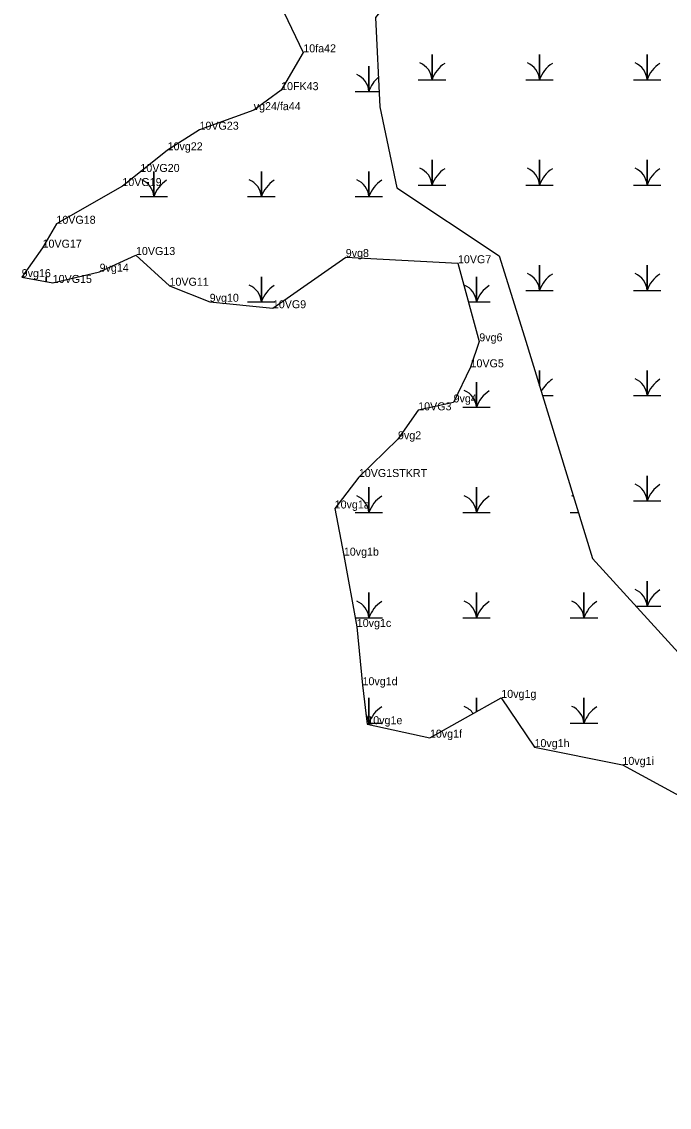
# Model space of a CAD drawing. Extents: x 2072529 to 2268796, y 436423 to 470397.
# Drawn here: x 2218413 to 2218818, y 449255 to 449933 of the extents above; entities that cross this region are included whole.
import ezdxf

# ---------------------------------------------------------------- set-up
doc = ezdxf.new("R2010")
doc.units = 0
for name, color, linetype in [('Exist Environmental Wetland Boundary', 7, 'Continuous'), ('Exist Environmental Wetland Boundary Cogo Comment', 7, 'Continuous'), ('Exist Environmental Wetland Boundary Cogo Point CELL', 7, 'Continuous'), ('Exist Hydro Jurisdictional Stream or Body of Water NEU Mitigable', 7, 'Continuous'), ('Exist Hydro Swamp or Marsh', 7, 'Continuous')]:
    doc.layers.add(name, color=color, linetype=linetype)

msp = doc.modelspace()

# ---------------------------------------------------------------- linework, layer by layer
at = {"layer": 'Exist Environmental Wetland Boundary'}
for points in [[(2218576.58, 449938.89), (2218588.8, 449913.82), (2218574.92, 449890.19), (2218557.81, 449877.7), (2218523.88, 449865.47), (2218503.95, 449852.61), (2218486.91, 449839.08), (2218475.66, 449830.27), (2218434.4, 449806.7), (2218425.75, 449791.75), (2218412.7, 449773.34), (2218432.08, 449769.73), (2218461.44, 449776.76), (2218484.17, 449787.18), (2218505.14, 449767.97), (2218530.27, 449757.96), (2218569.77, 449753.92), (2218615.36, 449785.92), (2218685.51, 449782.04), (2218698.88, 449733.24), (2218693.38, 449717.01), (2218682.81, 449695.07), (2218660.66, 449690.13), (2218648.02, 449672.03), (2218623.54, 449648.45)], [(2218623.54, 449648.45), (2218608.43, 449628.79), (2218614.15, 449599.32), (2218622.25, 449554.75), (2218625.83, 449518.36), (2218628.83, 449494), (2218667.98, 449485.58), (2218712.63, 449510.45), (2218733.38, 449479.68), (2218788.37, 449468.57)], [(2218788.37, 449468.57), (2218824.12, 449449.24), (2218880.96, 449410.75), (2218954.22, 449357.03), (2219012.6, 449309.82), (2219086.75, 449254.63)]]:
    msp.add_lwpolyline(points, dxfattribs=at)
at = {"layer": 'Exist Environmental Wetland Boundary Cogo Point CELL'}
for p, q in [((2218588.8, 449913.82), (2218588.8, 449913.82)), ((2218574.92, 449890.19), (2218574.92, 449890.19)), ((2218574.92, 449890.19), (2218574.92, 449890.19)), ((2218557.81, 449877.7), (2218557.81, 449877.7)), ((2218523.88, 449865.47), (2218523.88, 449865.47)), ((2218523.88, 449865.47), (2218523.88, 449865.47)), ((2218503.95, 449852.61), (2218503.95, 449852.61)), ((2218486.91, 449839.08), (2218486.91, 449839.08)), ((2218486.91, 449839.08), (2218486.91, 449839.08)), ((2218475.66, 449830.27), (2218475.66, 449830.27)), ((2218475.66, 449830.27), (2218475.66, 449830.27)), ((2218434.4, 449806.7), (2218434.4, 449806.7)), ((2218434.4, 449806.7), (2218434.4, 449806.7)), ((2218425.75, 449791.75), (2218425.75, 449791.75)), ((2218425.75, 449791.75), (2218425.75, 449791.75)), ((2218484.17, 449787.18), (2218484.17, 449787.18)), ((2218484.17, 449787.18), (2218484.17, 449787.18)), ((2218615.36, 449785.92), (2218615.36, 449785.92)), ((2218685.51, 449782.04), (2218685.51, 449782.04)), ((2218685.51, 449782.04), (2218685.51, 449782.04)), ((2218412.7, 449773.34), (2218412.7, 449773.34)), ((2218461.44, 449776.76), (2218461.44, 449776.76)), ((2218432.08, 449769.73), (2218432.08, 449769.73)), ((2218432.08, 449769.73), (2218432.08, 449769.73)), ((2218505.14, 449767.97), (2218505.14, 449767.97)), ((2218505.14, 449767.97), (2218505.14, 449767.97)), ((2218530.27, 449757.96), (2218530.27, 449757.96)), ((2218569.77, 449753.92), (2218569.77, 449753.92)), ((2218569.77, 449753.92), (2218569.77, 449753.92)), ((2218698.88, 449733.24), (2218698.88, 449733.24)), ((2218693.38, 449717.01), (2218693.38, 449717.01)), ((2218693.38, 449717.01), (2218693.38, 449717.01)), ((2218660.66, 449690.13), (2218660.66, 449690.13)), ((2218660.66, 449690.13), (2218660.66, 449690.13)), ((2218682.81, 449695.07), (2218682.81, 449695.07)), ((2218648.02, 449672.03), (2218648.02, 449672.03)), ((2218623.54, 449648.45), (2218623.54, 449648.45)), ((2218623.54, 449648.45), (2218623.54, 449648.45)), ((2218608.43, 449628.79), (2218608.43, 449628.79)), ((2218614.15, 449599.32), (2218614.15, 449599.32)), ((2218622.25, 449554.75), (2218622.25, 449554.75)), ((2218625.83, 449518.36), (2218625.83, 449518.36)), ((2218712.63, 449510.45), (2218712.63, 449510.45)), ((2218628.83, 449494), (2218628.83, 449494)), ((2218667.98, 449485.58), (2218667.98, 449485.58)), ((2218733.38, 449479.68), (2218733.38, 449479.68)), ((2218788.37, 449468.57), (2218788.37, 449468.57))]:
    msp.add_line(p, q, dxfattribs=at)
at = {"layer": 'Exist Hydro Jurisdictional Stream or Body of Water NEU Mitigable'}
msp.add_lwpolyline([(2218535.63, 450404.2), (2218554.25, 450332.33), (2218567.55, 450265.78), (2218567.55, 450228.51), (2218580.85, 450148.65), (2218591.49, 450066.12), (2218615.44, 450031.52), (2218650.02, 450012.88), (2218660.66, 449994.25), (2218652.68, 449959.64), (2218634.06, 449935.68), (2218636.72, 449879.78), (2218647.36, 449829.2), (2218711.2, 449786.61), (2218727.16, 449736.03), (2218769.73, 449597.6), (2218825.59, 449536.38), (2218892.1, 449475.15), (2218953.28, 449435.22), (2219051.71, 449381.98), (2219115.55, 449339.39), (2219162.87, 449300.4)], dxfattribs=at)
at = {"layer": 'Exist Hydro Swamp or Marsh'}
for points in [[(2218660.71, 449896.7), (2218669.31, 449896.7), (2218669.31, 449912.48), (2218669.31, 449896.7), (2218677.91, 449896.7)], [(2218727.96, 449896.7), (2218736.56, 449896.7), (2218736.56, 449912.48), (2218736.56, 449896.7), (2218745.16, 449896.7)], [(2218795.21, 449896.7), (2218803.81, 449896.7), (2218803.81, 449912.48), (2218803.81, 449896.7), (2218812.41, 449896.7)], [(2218621.23, 449889.45), (2218629.83, 449889.45), (2218629.83, 449905.23), (2218629.83, 449889.45), (2218636.26, 449889.45)], [(2218660.71, 449830.9), (2218669.31, 449830.9), (2218669.31, 449846.68), (2218669.31, 449830.9), (2218677.91, 449830.9)], [(2218727.96, 449830.9), (2218736.56, 449830.9), (2218736.56, 449846.68), (2218736.56, 449830.9), (2218745.16, 449830.9)], [(2218795.21, 449830.9), (2218803.81, 449830.9), (2218803.81, 449846.68), (2218803.81, 449830.9), (2218812.41, 449830.9)], [(2218486.73, 449823.65), (2218495.33, 449823.65), (2218495.33, 449839.43), (2218495.33, 449823.65), (2218503.93, 449823.65)], [(2218553.98, 449823.65), (2218562.58, 449823.65), (2218562.58, 449839.43), (2218562.58, 449823.65), (2218571.18, 449823.65)], [(2218621.23, 449823.65), (2218629.83, 449823.65), (2218629.83, 449839.43), (2218629.83, 449823.65), (2218638.43, 449823.65)], [(2218727.96, 449765.1), (2218736.56, 449765.1), (2218736.56, 449780.88), (2218736.56, 449765.1), (2218745.16, 449765.1)], [(2218795.21, 449765.1), (2218803.81, 449765.1), (2218803.81, 449780.88), (2218803.81, 449765.1), (2218812.41, 449765.1)], [(2218428.08, 449770.47), (2218428.08, 449773.63), (2218428.08, 449770.47)], [(2218553.98, 449757.85), (2218562.58, 449757.85), (2218562.58, 449773.63), (2218562.58, 449757.85), (2218571.18, 449757.85)], [(2218692.14, 449757.85), (2218697.08, 449757.85), (2218697.08, 449773.63), (2218697.08, 449757.85), (2218705.68, 449757.85)], [(2218736.56, 449705.47), (2218736.56, 449715.08), (2218736.56, 449705.47)], [(2218795.21, 449699.3), (2218803.81, 449699.3), (2218803.81, 449715.08), (2218803.81, 449699.3), (2218812.41, 449699.3)], [(2218688.48, 449692.05), (2218697.08, 449692.05), (2218697.08, 449707.83), (2218697.08, 449692.05), (2218705.68, 449692.05)], [(2218738.46, 449699.3), (2218745.16, 449699.3)], [(2218795.21, 449633.5), (2218803.81, 449633.5), (2218803.81, 449649.28), (2218803.81, 449633.5), (2218812.41, 449633.5)], [(2218621.23, 449626.25), (2218629.83, 449626.25), (2218629.83, 449642.03), (2218629.83, 449626.25), (2218638.43, 449626.25)], [(2218688.48, 449626.25), (2218697.08, 449626.25), (2218697.08, 449642.03), (2218697.08, 449626.25), (2218705.68, 449626.25)], [(2218755.73, 449626.25), (2218760.92, 449626.25)], [(2218797.01, 449567.7), (2218803.81, 449567.7), (2218803.81, 449583.48), (2218803.81, 449567.7), (2218812.41, 449567.7)], [(2218621.23, 449560.45), (2218629.83, 449560.45), (2218629.83, 449576.23), (2218629.83, 449560.45), (2218638.43, 449560.45)], [(2218688.48, 449560.45), (2218697.08, 449560.45), (2218697.08, 449576.23), (2218697.08, 449560.45), (2218705.68, 449560.45)], [(2218755.73, 449560.45), (2218764.33, 449560.45), (2218764.33, 449576.23), (2218764.33, 449560.45), (2218772.93, 449560.45)], [(2218628.75, 449494.65), (2218629.83, 449494.65), (2218629.83, 449510.43), (2218629.83, 449494.65), (2218638.43, 449494.65)], [(2218697.08, 449501.79), (2218697.08, 449510.43), (2218697.08, 449501.79)], [(2218755.73, 449494.65), (2218764.33, 449494.65), (2218764.33, 449510.43), (2218764.33, 449494.65), (2218772.93, 449494.65)]]:
    msp.add_lwpolyline(points, dxfattribs=at)
for centre, radius, start, end in [((2218657.04, 449895.81), 12.3, 4.14034, 67.53497), ((2218687.55, 449890.64), 19.22, 122.12745, 161.62219), ((2218724.29, 449895.81), 12.3, 4.14034, 67.53497), ((2218754.8, 449890.64), 19.22, 122.12745, 161.62219), ((2218791.54, 449895.81), 12.3, 4.14034, 67.53497), ((2218822.05, 449890.64), 19.22, 122.12745, 161.62219), ((2218617.56, 449888.56), 12.3, 4.14034, 67.53497), ((2218648.07, 449883.39), 19.22, 129.50872, 161.62219), ((2218657.04, 449830.01), 12.3, 4.14034, 67.53497), ((2218687.55, 449824.84), 19.22, 122.12745, 161.62219), ((2218724.29, 449830.01), 12.3, 4.14034, 67.53497), ((2218754.8, 449824.84), 19.22, 122.12745, 161.62219), ((2218791.54, 449830.01), 12.3, 4.14034, 67.53497), ((2218822.05, 449824.84), 19.22, 122.12745, 161.62219), ((2218483.06, 449822.76), 12.3, 4.14034, 67.53497), ((2218513.57, 449817.59), 19.22, 122.12745, 161.62219), ((2218550.31, 449822.76), 12.3, 4.14034, 67.53497), ((2218580.82, 449817.59), 19.22, 122.12745, 161.62219), ((2218617.56, 449822.76), 12.3, 4.14034, 67.53497), ((2218648.07, 449817.59), 19.22, 122.12745, 161.62219), ((2218724.29, 449764.21), 12.3, 4.14034, 67.53497), ((2218754.8, 449759.04), 19.22, 122.12745, 161.62219), ((2218791.54, 449764.21), 12.3, 4.14034, 67.53497), ((2218822.05, 449759.04), 19.22, 122.12745, 161.62219), ((2218550.31, 449756.96), 12.3, 4.14034, 67.53497), ((2218580.82, 449751.79), 19.22, 122.12745, 161.62219), ((2218684.81, 449756.96), 12.3, 4.14034, 67.53497), ((2218715.32, 449751.79), 19.22, 122.12745, 161.62219), ((2218754.8, 449693.24), 19.22, 122.12745, 153.14806), ((2218791.54, 449698.41), 12.3, 4.14034, 67.53497), ((2218822.05, 449693.24), 19.22, 122.12745, 161.62219), ((2218684.81, 449691.16), 12.3, 4.14034, 67.53497), ((2218715.32, 449685.99), 19.22, 122.12745, 161.62219), ((2218791.54, 449632.61), 12.3, 4.14034, 67.53497), ((2218822.05, 449627.44), 19.22, 122.12745, 161.62219), ((2218617.56, 449625.36), 12.3, 4.14034, 67.53497), ((2218648.07, 449620.19), 19.22, 122.12745, 161.62219), ((2218684.81, 449625.36), 12.3, 4.14034, 67.53497), ((2218715.32, 449620.19), 19.22, 122.12745, 161.62219), ((2218752.06, 449625.36), 12.3, 61.87866, 67.53497), ((2218791.54, 449566.81), 12.3, 4.14034, 67.53497), ((2218822.05, 449561.64), 19.22, 122.12745, 161.62219), ((2218617.56, 449559.56), 12.3, 4.14034, 67.53497), ((2218648.07, 449554.39), 19.22, 122.12745, 161.62219), ((2218684.81, 449559.56), 12.3, 4.14034, 67.53497), ((2218715.32, 449554.39), 19.22, 122.12745, 161.62219), ((2218752.06, 449559.56), 12.3, 4.14034, 67.53497), ((2218782.57, 449554.39), 19.22, 122.12745, 161.62219), ((2218617.56, 449493.76), 12.3, 4.14034, 31.27311), ((2218648.07, 449488.59), 19.22, 122.12745, 161.62219), ((2218684.81, 449493.76), 12.3, 33.98168, 67.53497), ((2218752.06, 449493.76), 12.3, 4.14034, 67.53497), ((2218782.57, 449488.59), 19.22, 122.12745, 161.62219)]:
    msp.add_arc(centre, radius, start, end, dxfattribs=at)

# ---------------------------------------------------------------- texts
at = {"layer": 'Exist Environmental Wetland Boundary Cogo Comment'}
for s, p in [('10fa42', (2218588.8, 449913.82)), ('10FK43', (2218574.92, 449890.19)), ('vg24/fa44', (2218557.81, 449877.7)), ('10VG23', (2218523.88, 449865.47)), ('10vg22', (2218503.95, 449852.61)), ('10VG20', (2218486.91, 449839.08)), ('10VG19', (2218475.66, 449830.27)), ('10VG18', (2218434.4, 449806.7)), ('10VG17', (2218425.75, 449791.75)), ('10VG13', (2218484.17, 449787.18)), ('9vg8', (2218615.36, 449785.92)), ('10VG7', (2218685.51, 449782.04)), ('9vg16', (2218412.7, 449773.34)), ('9vg14', (2218461.44, 449776.76)), ('10VG15', (2218432.08, 449769.73)), ('10VG11', (2218505.14, 449767.97)), ('9vg10', (2218530.27, 449757.96)), ('10VG9', (2218569.77, 449753.92)), ('9vg6', (2218698.88, 449733.24)), ('10VG5', (2218693.38, 449717.01)), ('9vg4', (2218682.81, 449695.07)), ('10VG3', (2218660.66, 449690.13)), ('9vg2', (2218648.02, 449672.03)), ('10VG1STKRT', (2218623.54, 449648.45)), ('10vg1a', (2218608.43, 449628.79)), ('10vg1b', (2218614.15, 449599.32)), ('10vg1c', (2218622.25, 449554.75)), ('10vg1d', (2218625.83, 449518.36)), ('10vg1g', (2218712.63, 449510.45)), ('10vg1e', (2218628.83, 449494)), ('10vg1f', (2218667.98, 449485.58)), ('10vg1h', (2218733.38, 449479.68)), ('10vg1i', (2218788.37, 449468.57))]:
    msp.add_text(s, height=5, dxfattribs=at).set_placement(p)

doc.saveas('drawing.dxf')
